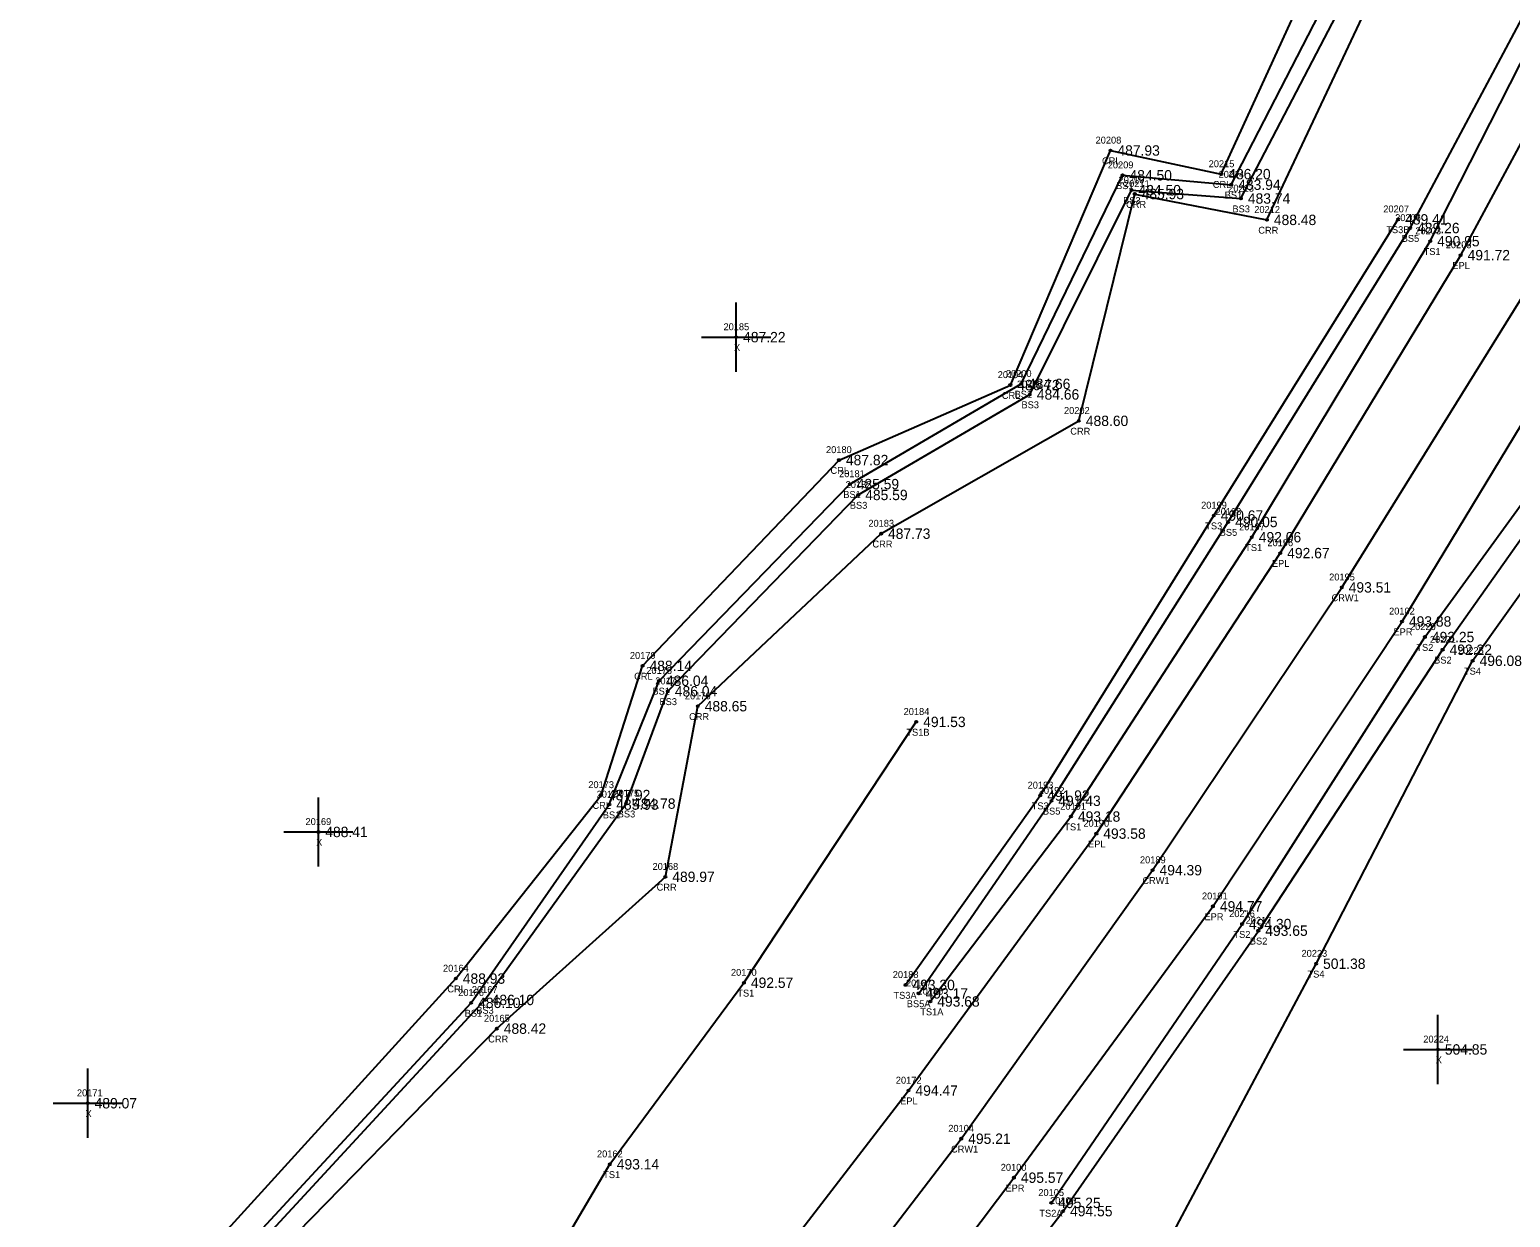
# Model space of a CAD drawing. Extents: x 1649406 to 1650436, y 896752 to 898178.
# Drawn here: x 1649581.2 to 1649795.4, y 897096.1 to 897267.9 of the extents above; entities that cross this region are included whole.
import ezdxf

# ---------------------------------------------------------------- set-up
doc = ezdxf.new("R2010")
doc.units = 0
for name, color, linetype in [('RD_DTM_BkLn1', 7, 'Continuous'), ('RD_DTM_BkLn2', 7, 'Continuous'), ('RD_DTM_BkLn_txCode', 7, 'Continuous'), ('RD_EX_H2O', 7, 'Continuous'), ('RD_EX_H2O_txCode', 7, 'Continuous'), ('RD_EX_Misc', 7, 'Continuous'), ('RD_EX_Misc_txCode', 7, 'Continuous'), ('RD_EX_Road', 7, 'Continuous'), ('RD_EX_Road_txCode', 7, 'Continuous'), ('RD_EX_TX_H2O_ELEV', 7, 'Continuous'), ('RD_EX_TX_Misc_ELEV', 7, 'Continuous'), ('RD_EX_TX_Road_ELEV', 7, 'Continuous'), ('RD_HC_Survey_ELEV', 7, 'Continuous'), ('RD_HC_Survey_txCode', 7, 'Continuous'), ('RD_SMD_Locator', 7, 'Continuous')]:
    doc.layers.add(name, color=color, linetype=linetype)

msp = doc.modelspace()

# ---------------------------------------------------------------- linework, layer by layer
at = {"layer": 'RD_DTM_BkLn1'}
msp.add_lwpolyline([(1649466.79, 896799.14), (1649494.97, 896834.25), (1649557.53, 896909.97), (1649590.88, 896950.41), (1649622.36, 896988.16), (1649622.36, 896988.48), (1649654.33, 897027.92), (1649685.38, 897067.52), (1649715.96, 897107.48), (1649743.64, 897146.32), (1649771.01, 897187.23), (1649797.64, 897230.08), (1649820.89, 897273.98), (1649842.91, 897321.22), (1649862.74, 897368.05), (1649877.08, 897408.66)], dxfattribs=at)
at = {"layer": 'RD_DTM_BkLn2'}
for points in [[(1649604.6, 897005.75), (1649602.47, 897009.39), (1649602.3, 897017.91), (1649611.46, 897066.62), (1649609.91, 897087.35), (1649647.02, 897127.55), (1649667.48, 897155.95), (1649673.52, 897172.2), (1649701.06, 897200.6), (1649725.89, 897215.14), (1649740.6, 897244.69), (1649756.42, 897243.48), (1649789.18, 897306.38), (1649812.44, 897341.7), (1649825.72, 897367.05), (1649832.43, 897399.23), (1649835.49, 897415.79), (1649852.17, 897423.43), (1649870.24, 897429.91)], [(1649709.8, 897128.5), (1649729, 897156.36), (1649754.58, 897196.69), (1649780.91, 897239.21), (1649804.81, 897284.08), (1649825.46, 897331.72), (1649840.02, 897380.03), (1649851.88, 897417.91)], [(1649711.48, 897127.33), (1649731.83, 897154.08), (1649758, 897194.49), (1649783.81, 897237.31), (1649806.95, 897282.89), (1649830.65, 897328.8), (1649845.62, 897375.19), (1649854.76, 897409.92), (1649862.43, 897417.84), (1649895.58, 897416.19)], [(1649603.2, 897003.67), (1649600.88, 897008.96), (1649600.6, 897018.07), (1649608.4, 897066.47), (1649606.62, 897085.55), (1649645.06, 897127.13), (1649665.04, 897155.81), (1649672.23, 897173.72), (1649699.83, 897202.17), (1649724.61, 897216.67), (1649739.3, 897246.84), (1649755.02, 897245.48), (1649787.66, 897308.84)], [(1649689.03, 896955.15), (1649675.54, 896986.1), (1649671.09, 897009.54), (1649678.93, 897030.09), (1649699.37, 897056.41), (1649730.7, 897097.01), (1649758.94, 897137.57), (1649785.6, 897178.21), (1649814.8, 897219.5), (1649846.42, 897264.34)], [(1649728.99, 897098.19), (1649756.58, 897138.53), (1649783.04, 897180.05), (1649813.23, 897221.59), (1649842.24, 897265.02)], [(1649692.17, 896958.45), (1649679.46, 896987.93), (1649676.76, 897009.49), (1649682.34, 897025.02), (1649708.77, 897048.86), (1649742.68, 897086.45), (1649767.3, 897132.79), (1649789.94, 897176.61), (1649819.17, 897217.64), (1649850.28, 897262.86)], [(1649707.89, 897129.72), (1649727.39, 897157.12), (1649752.5, 897197.62), (1649779.17, 897240.47)], [(1649610.78, 897003.58), (1649623.9, 897019.02), (1649632.33, 897048.06), (1649665.12, 897103.78), (1649684.52, 897130.04), (1649709.45, 897167.77)]]:
    msp.add_lwpolyline(points, dxfattribs=at)
at = {"layer": 'RD_EX_H2O'}
for points in [[(1649610.78, 897003.58), (1649606.65, 897007.8), (1649603.49, 897018.01), (1649613.66, 897065.71), (1649613.8, 897087.62), (1649648.77, 897123.4), (1649673.15, 897145.36), (1649677.84, 897170.04), (1649704.36, 897195), (1649732.98, 897211.32), (1649741.05, 897244.13), (1649760.18, 897240.39), (1649790.48, 897304.8), (1649814.66, 897340.98), (1649827.92, 897366.62), (1649835.63, 897392.05), (1649839.2, 897413.36), (1649851.88, 897417.91), (1649868.27, 897424.7)], [(1649605.92, 896999), (1649598.21, 896999.47), (1649594.11, 897011.28), (1649598.36, 897025.11), (1649605.96, 897065.98), (1649602.09, 897085.85), (1649642.84, 897130.64), (1649663.84, 897157.19), (1649669.86, 897175.88), (1649698.27, 897205.65), (1649723.06, 897216.5), (1649737.55, 897250.43), (1649753.58, 897247.01), (1649784.63, 897314.89)]]:
    msp.add_lwpolyline(points, dxfattribs=at)
at = {"layer": 'RD_EX_Misc'}
for p, q in [((1649683.4, 897218.43), (1649683.4, 897228.43)), ((1649678.4, 897223.43), (1649688.4, 897223.43)), ((1649622.95, 897146.85), (1649622.95, 897156.85)), ((1649617.95, 897151.85), (1649627.95, 897151.85)), ((1649784.92, 897115.39), (1649784.92, 897125.39)), ((1649779.92, 897120.39), (1649789.92, 897120.39)), ((1649589.58, 897107.61), (1649589.58, 897117.61)), ((1649584.58, 897112.61), (1649594.58, 897112.61))]:
    msp.add_line(p, q, dxfattribs=at)
at = {"layer": 'RD_EX_Road'}
for points in [[(1649459.38, 896805.71), (1649486.55, 896839.62), (1649513.65, 896873.34), (1649538.22, 896902.56), (1649549.43, 896916.62), (1649583.1, 896957.27), (1649614.8, 896995.02), (1649647.06, 897035.69), (1649677.62, 897074.51), (1649708.33, 897114.44), (1649735.5, 897151.61), (1649762.11, 897192.19), (1649788.21, 897235.29), (1649812.17, 897279.73), (1649834.32, 897326.54), (1649852.94, 897371.82), (1649867.51, 897411.96)], [(1649474.75, 896792.65), (1649502.78, 896827.35), (1649565.2, 896903.92), (1649598.28, 896943.71), (1649629.8, 896982.26), (1649667.92, 897029.33), (1649693.13, 897061.44), (1649723.58, 897101.84), (1649752.37, 897141.09), (1649779.72, 897182.3), (1649806.12, 897225.84), (1649830.13, 897270.79), (1649852.39, 897317.43), (1649871.98, 897364.35), (1649886.55, 897406.09)]]:
    msp.add_lwpolyline(points, dxfattribs=at)
at = {"layer": 'RD_SMD_Locator'}
for centre in [(1649737.55, 897250.43), (1649739.3, 897246.84), (1649753.58, 897247.01), (1649740.6, 897244.69), (1649755.02, 897245.48), (1649741.05, 897244.13), (1649756.42, 897243.48), (1649760.18, 897240.39), (1649779.17, 897240.47), (1649780.91, 897239.21), (1649783.81, 897237.31), (1649788.21, 897235.29), (1649683.4, 897223.43), (1649724.61, 897216.67), (1649723.06, 897216.5), (1649725.89, 897215.14), (1649732.98, 897211.32), (1649698.27, 897205.65), (1649699.83, 897202.17), (1649701.06, 897200.6), (1649752.5, 897197.62), (1649754.58, 897196.69), (1649704.36, 897195), (1649758, 897194.49), (1649762.11, 897192.19), (1649771.01, 897187.23), (1649779.72, 897182.3), (1649783.04, 897180.05), (1649785.6, 897178.21), (1649669.86, 897175.88), (1649789.94, 897176.61), (1649672.23, 897173.72), (1649673.52, 897172.2), (1649677.84, 897170.04), (1649709.45, 897167.77), (1649663.84, 897157.19), (1649727.39, 897157.12), (1649665.04, 897155.81), (1649667.48, 897155.95), (1649729, 897156.36), (1649731.83, 897154.08), (1649622.95, 897151.85), (1649735.5, 897151.61), (1649743.64, 897146.32), (1649673.15, 897145.36), (1649752.37, 897141.09), (1649756.58, 897138.53), (1649758.94, 897137.57), (1649767.3, 897132.79), (1649642.84, 897130.64), (1649684.52, 897130.04), (1649707.89, 897129.72), (1649645.06, 897127.13), (1649647.02, 897127.55), (1649709.8, 897128.5), (1649711.48, 897127.33), (1649648.77, 897123.4), (1649784.92, 897120.39), (1649708.33, 897114.44), (1649589.58, 897112.61), (1649715.96, 897107.48), (1649665.12, 897103.78), (1649723.58, 897101.84), (1649728.99, 897098.19), (1649730.7, 897097.01)]:
    msp.add_circle(centre, 0.15, dxfattribs=at)

# ---------------------------------------------------------------- texts
at = {"layer": 'RD_DTM_BkLn_txCode'}
for s, p in [('20209', (1649737.15, 897247.84)), ('20210', (1649738.72, 897245.69)), ('20214', (1649753.18, 897246.48)), ('BS1', (1649738.36, 897244.84)), ('20213', (1649754.58, 897244.48)), ('BS3', (1649739.37, 897242.69)), ('BS1', (1649754.07, 897243.48)), ('BS3', (1649755.19, 897241.48)), ('20207', (1649777.01, 897241.47)), ('20206', (1649778.73, 897240.21)), ('TS3B', (1649777.45, 897238.47)), ('BS5', (1649779.68, 897237.21)), ('20203', (1649781.65, 897238.31)), ('TS1', (1649782.85, 897235.31)), ('20200', (1649722.41, 897217.67)), ('20201', (1649724.02, 897216.14)), ('BS1', (1649723.67, 897214.67)), ('BS3', (1649724.67, 897213.14)), ('20181', (1649698.28, 897203.17)), ('20182', (1649699.23, 897201.6)), ('BS1', (1649698.89, 897200.17)), ('BS3', (1649699.84, 897198.6)), ('20199', (1649750.66, 897198.62)), ('20198', (1649752.75, 897197.69)), ('TS3', (1649751.26, 897195.62)), ('BS5', (1649753.35, 897194.69)), ('20197', (1649756.16, 897195.49)), ('TS1', (1649757.04, 897192.49)), ('20220', (1649780.88, 897181.05)), ('TS2', (1649781.8, 897178.05)), ('20221', (1649783.76, 897179.21)), ('20225', (1649787.82, 897177.61)), ('BS2', (1649784.37, 897176.21)), ('20178', (1649670.39, 897174.72)), ('20177', (1649671.69, 897173.2)), ('TS4', (1649788.69, 897174.61)), ('BS1', (1649671.28, 897171.72)), ('BS3', (1649672.3, 897170.2)), ('20184', (1649707.62, 897168.77)), ('TS1B', (1649708.02, 897165.77)), ('20193', (1649725.56, 897158.12)), ('20174', (1649663.21, 897156.81)), ('20175', (1649665.65, 897156.95)), ('20192', (1649727.17, 897157.36)), ('BS1', (1649664.1, 897153.81)), ('BS3', (1649666.26, 897153.95)), ('TS3', (1649726.15, 897155.12)), ('BS5', (1649727.77, 897154.36)), ('20191', (1649730.28, 897155.08)), ('TS1', (1649730.87, 897152.08)), ('20216', (1649754.72, 897139.53)), ('TS2', (1649755.34, 897136.53)), ('20217', (1649757.1, 897138.57)), ('BS2', (1649757.71, 897135.57)), ('20223', (1649765.18, 897133.79)), ('20170', (1649682.64, 897131.04)), ('20188', (1649706.05, 897130.72)), ('TS4', (1649766.05, 897130.79)), ('20166', (1649643.18, 897128.13)), ('20167', (1649645.16, 897128.55)), ('TS1', (1649683.56, 897128.04)), ('20187', (1649707.96, 897129.5)), ('20186', (1649709.62, 897128.33)), ('TS3A', (1649706.15, 897127.72)), ('BS5A', (1649708.08, 897126.5)), ('BS1', (1649644.12, 897125.13)), ('BS3', (1649645.79, 897125.55)), ('TS1A', (1649710.03, 897125.33)), ('20162', (1649663.26, 897104.78)), ('TS1', (1649664.16, 897101.78)), ('20105', (1649727.11, 897099.19)), ('20106', (1649728.81, 897098.01)), ('TS2A', (1649727.26, 897096.19))]:
    msp.add_text(s, height=1, dxfattribs=at).set_placement(p)
at = {"layer": 'RD_EX_H2O_txCode'}
for s, p in [('20208', (1649735.39, 897251.43)), ('CRL', (1649736.32, 897248.43)), ('20215', (1649751.75, 897248.01)), ('20211', (1649739.5, 897245.13)), ('CRL', (1649752.35, 897245.01)), ('CRR', (1649739.8, 897242.13)), ('20212', (1649758.35, 897241.39)), ('CRR', (1649758.93, 897238.39)), ('20194', (1649721.23, 897217.5)), ('CRL', (1649721.83, 897214.5)), ('20202', (1649730.82, 897212.32)), ('CRR', (1649731.73, 897209.32)), ('20180', (1649696.39, 897206.65)), ('CRL', (1649697.04, 897203.65)), ('20183', (1649702.52, 897196)), ('CRR', (1649703.11, 897193)), ('20179', (1649668.02, 897176.88)), ('CRL', (1649668.63, 897173.88)), ('20176', (1649675.98, 897171.04)), ('CRR', (1649676.58, 897168.04)), ('20173', (1649662, 897158.19)), ('CRL', (1649662.61, 897155.19)), ('20168', (1649671.29, 897146.36)), ('CRR', (1649671.89, 897143.36)), ('20164', (1649640.98, 897131.64)), ('CRL', (1649641.61, 897128.64)), ('20165', (1649646.91, 897124.4)), ('CRR', (1649647.52, 897121.4))]:
    msp.add_text(s, height=1, dxfattribs=at).set_placement(p)
at = {"layer": 'RD_EX_Misc_txCode'}
for s, p in [('20185', (1649681.56, 897224.43)), ('X', (1649683.08, 897221.43)), ('20169', (1649621.09, 897152.85)), ('X', (1649622.63, 897149.85)), ('20224', (1649782.8, 897121.39)), ('X', (1649784.6, 897118.39)), ('20171', (1649588.02, 897113.61)), ('X', (1649589.26, 897110.61))]:
    msp.add_text(s, height=1, dxfattribs=at).set_placement(p)
at = {"layer": 'RD_EX_Road_txCode'}
for s, p in [('20205', (1649786.05, 897236.29)), ('EPL', (1649787.01, 897233.29)), ('20196', (1649760.25, 897193.19)), ('EPL', (1649760.9, 897190.19)), ('20102', (1649777.85, 897183.3)), ('EPR', (1649778.49, 897180.3)), ('20190', (1649733.63, 897152.61)), ('EPL', (1649734.3, 897149.61)), ('20101', (1649750.78, 897142.09)), ('EPR', (1649751.14, 897139.09)), ('20172', (1649706.49, 897115.44)), ('EPL', (1649707.12, 897112.44)), ('20100', (1649721.67, 897102.84)), ('EPR', (1649722.35, 897099.84))]:
    msp.add_text(s, height=1, dxfattribs=at).set_placement(p)
at = {"layer": 'RD_EX_TX_H2O_ELEV'}
for s, p in [('487.93', (1649738.55, 897249.68)), ('486.20', (1649754.58, 897246.26)), ('485.93', (1649742.05, 897243.38)), ('488.48', (1649761.18, 897239.64)), ('486.72', (1649724.06, 897215.75)), ('488.60', (1649733.98, 897210.57)), ('487.82', (1649699.27, 897204.9)), ('487.73', (1649705.36, 897194.25)), ('488.14', (1649670.86, 897175.13)), ('488.65', (1649678.84, 897169.29)), ('487.92', (1649664.84, 897156.44)), ('489.97', (1649674.15, 897144.61)), ('488.93', (1649643.84, 897129.89)), ('488.42', (1649649.77, 897122.65))]:
    msp.add_text(s, height=1.5, dxfattribs=at).set_placement(p)
at = {"layer": 'RD_EX_TX_Misc_ELEV'}
for s, p in [('484.50', (1649740.3, 897246.09)), ('484.50', (1649741.6, 897243.94)), ('483.94', (1649756.02, 897244.73)), ('483.74', (1649757.42, 897242.73)), ('489.41', (1649780.17, 897239.72)), ('489.26', (1649781.91, 897238.46)), ('490.95', (1649784.81, 897236.56)), ('487.22', (1649684.4, 897222.68)), ('484.66', (1649725.61, 897215.92)), ('484.66', (1649726.89, 897214.39)), ('485.59', (1649700.83, 897201.42)), ('485.59', (1649702.06, 897199.85)), ('490.67', (1649753.5, 897196.87)), ('490.05', (1649755.58, 897195.94)), ('492.06', (1649759, 897193.74)), ('493.25', (1649784.04, 897179.3)), ('492.22', (1649786.6, 897177.46)), ('496.08', (1649790.94, 897175.86)), ('486.04', (1649673.23, 897172.97)), ('486.04', (1649674.52, 897171.45)), ('491.53', (1649710.45, 897167.02)), ('491.92', (1649728.39, 897156.37)), ('491.43', (1649730, 897155.61)), ('485.93', (1649666.04, 897155.06)), ('484.78', (1649668.48, 897155.2)), ('493.18', (1649732.83, 897153.33)), ('488.41', (1649623.95, 897151.1)), ('494.30', (1649757.58, 897137.78)), ('493.65', (1649759.94, 897136.82)), ('501.38', (1649768.3, 897132.04)), ('492.57', (1649685.52, 897129.29)), ('493.30', (1649708.89, 897128.97)), ('493.17', (1649710.8, 897127.75)), ('486.10', (1649646.06, 897126.38)), ('486.10', (1649648.02, 897126.8)), ('493.68', (1649712.48, 897126.58)), ('504.85', (1649785.92, 897119.64)), ('489.07', (1649590.58, 897111.86)), ('493.14', (1649666.12, 897103.03)), ('495.25', (1649729.99, 897097.44)), ('494.55', (1649731.7, 897096.26))]:
    msp.add_text(s, height=1.5, dxfattribs=at).set_placement(p)
at = {"layer": 'RD_EX_TX_Road_ELEV'}
for s, p in [('491.72', (1649789.21, 897234.54)), ('492.67', (1649763.11, 897191.44)), ('493.88', (1649780.72, 897181.55)), ('493.58', (1649736.5, 897150.86)), ('494.77', (1649753.37, 897140.34)), ('494.47', (1649709.33, 897113.69)), ('495.57', (1649724.58, 897101.09))]:
    msp.add_text(s, height=1.5, dxfattribs=at).set_placement(p)
at = {"layer": 'RD_HC_Survey_ELEV'}
for s, p in [('493.51', (1649772.01, 897186.48)), ('494.39', (1649744.64, 897145.57)), ('495.21', (1649716.96, 897106.73))]:
    msp.add_text(s, height=1.5, dxfattribs=at).set_placement(p)
at = {"layer": 'RD_HC_Survey_txCode'}
for s, p in [('20195', (1649769.18, 897188.23)), ('CRW1', (1649769.53, 897185.23)), ('20189', (1649741.81, 897147.32)), ('CRW1', (1649742.16, 897144.32)), ('20104', (1649714.08, 897108.48)), ('CRW1', (1649714.48, 897105.48))]:
    msp.add_text(s, height=1, dxfattribs=at).set_placement(p)

doc.saveas('drawing.dxf')
